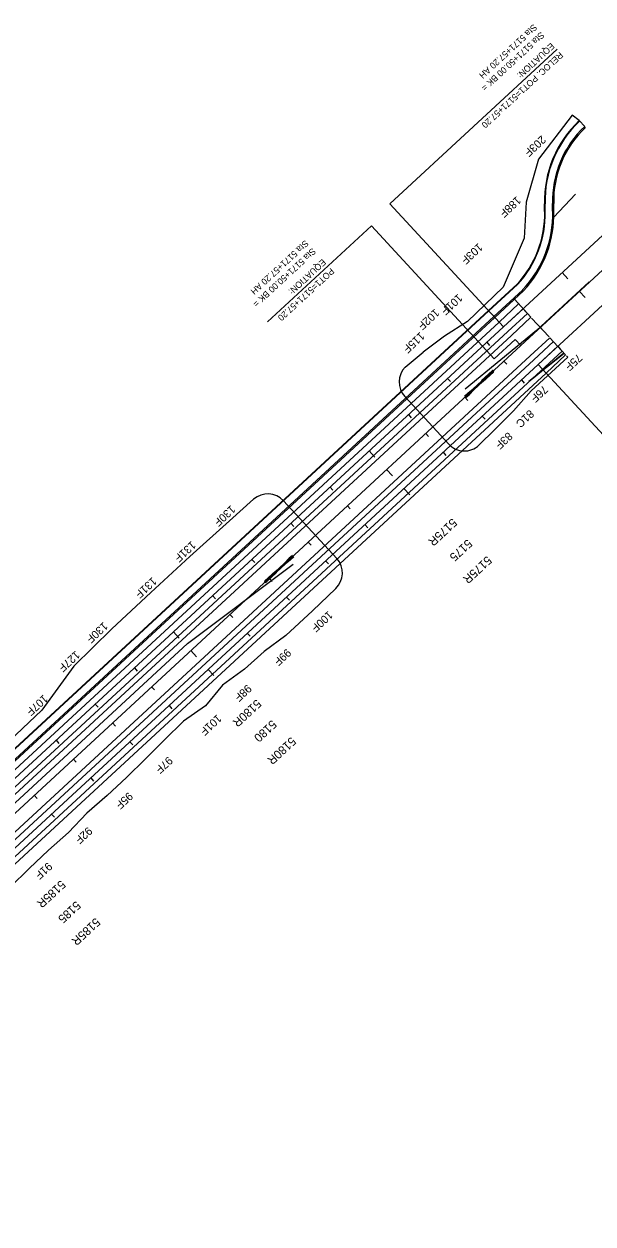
# Model space of a CAD drawing. Extents: x 2160876 to 2175625, y 601634 to 617693.
# Drawn here: x 2171308 to 2172375, y 612093 to 614343 of the extents above; entities that cross this region are included whole.
import ezdxf

# ---------------------------------------------------------------- set-up
doc = ezdxf.new("R2010")
doc.units = 0
for name, color, linetype in [('RD_HC_Cl', 7, 'Continuous'), ('RD_HC_CL_Rel', 7, 'Continuous'), ('RD_HC_Data', 7, 'Continuous'), ('RD_HC_Data_Rel', 7, 'Continuous'), ('RD_HC_Data_Tic', 7, 'Continuous'), ('RD_HC_Data_Tic_Rel', 7, 'Continuous'), ('RD_HC_TX_Rel_Sta50', 7, 'Continuous'), ('RD_HC_TX_Sta50', 7, 'Continuous'), ('RD_PD_CstnLmt', 7, 'Continuous'), ('RD_PD_Fence', 7, 'Continuous'), ('RD_PD_Final_LnLine', 7, 'Continuous'), ('RD_PD_Final_TrvlWay', 7, 'Continuous'), ('RD_PD_GR', 7, 'Continuous'), ('RD_PD_MedBWall', 7, 'Continuous'), ('RD_PD_MedGR', 7, 'Continuous')]:
    doc.layers.add(name, color=color, linetype=linetype)

msp = doc.modelspace()

# ---------------------------------------------------------------- linework, layer by layer
at = {"layer": 'RD_HC_Cl'}
for p, q in [((2172654, 614122.3), (2172239.9, 613739.9)), ((2172239.9, 613739.9), (2163704.8, 605858.6))]:
    msp.add_line(p, q, dxfattribs=at)
at = {"layer": 'RD_HC_CL_Rel'}
for p, q in [((2172621.5, 614157.6), (2172207.3, 613775.1)), ((2172686.6, 614087), (2172272.5, 613704.6)), ((2172207.3, 613775.1), (2170395.2, 612101.8)), ((2172272.5, 613704.6), (2170460.3, 612031.3))]:
    msp.add_line(p, q, dxfattribs=at)
at = {"layer": 'RD_HC_Data'}
for p, q in [((2171994.4, 614005.8), (2172308.2, 614295.6)), ((2171959.5, 613964.4), (2171764.8, 613784.6)), ((2172239.9, 613739.9), (2172229.2, 613751.5))]:
    msp.add_line(p, q, dxfattribs=at)
msp.add_lwpolyline([(2172229.2, 613751.5), (2172189.7, 613715.1), (2171959.5, 613964.4)], dxfattribs=at)
at = {"layer": 'RD_HC_Data_Rel'}
for p, q in [((2172207.3, 613775.1), (2171994.4, 614005.8)), ((2172630.4, 613317), (2172272.5, 613704.6))]:
    msp.add_line(p, q, dxfattribs=at)
at = {"layer": 'RD_HC_Data_Tic'}
for p, q in [((2172350.1, 613841.6), (2172360.9, 613829.9)), ((2172276.6, 613773.8), (2172282, 613767.9)), ((2172208.4, 613710.8), (2172213.9, 613705)), ((2172135, 613643), (2172140.4, 613637.1)), ((2172061.5, 613575.2), (2172066.9, 613569.3)), ((2171988, 613507.3), (2171998.9, 613495.6)), ((2171914.6, 613439.5), (2171920, 613433.6)), ((2171841.1, 613371.6), (2171846.5, 613365.8)), ((2171767.6, 613303.8), (2171773.1, 613297.9)), ((2171694.2, 613236), (2171699.6, 613230.1)), ((2171620.7, 613168.1), (2171631.6, 613156.4)), ((2171547.2, 613100.3), (2171552.7, 613094.4)), ((2171473.8, 613032.4), (2171479.2, 613026.6)), ((2171400.3, 612964.6), (2171405.7, 612958.7)), ((2171326.8, 612896.7), (2171332.2, 612890.9))]:
    msp.add_line(p, q, dxfattribs=at)
at = {"layer": 'RD_HC_Data_Tic_Rel'}
for p, q in [((2172317.5, 613876.9), (2172328.4, 613865.1)), ((2172244.1, 613809.1), (2172249.5, 613803.2)), ((2172175.9, 613746.1), (2172181.3, 613740.2)), ((2172309.2, 613738.5), (2172314.6, 613732.7)), ((2172102.4, 613678.3), (2172107.8, 613672.4)), ((2172241, 613675.6), (2172246.4, 613669.7)), ((2172028.9, 613610.4), (2172034.4, 613604.5)), ((2172167.5, 613607.7), (2172173, 613601.9)), ((2171955.5, 613542.6), (2171966.3, 613530.8)), ((2172094.1, 613539.9), (2172099.5, 613534)), ((2171882, 613474.7), (2171887.4, 613468.9)), ((2172020.6, 613472.1), (2172031.5, 613460.3)), ((2171808.5, 613406.9), (2171814, 613401)), ((2171947.1, 613404.2), (2171952.6, 613398.3)), ((2171735.1, 613339.1), (2171740.5, 613333.2)), ((2171873.7, 613336.4), (2171879.1, 613330.5)), ((2171661.6, 613271.2), (2171667, 613265.3)), ((2171800.2, 613268.5), (2171805.6, 613262.7)), ((2171588.1, 613203.4), (2171599, 613191.6)), ((2171726.7, 613200.7), (2171732.2, 613194.8)), ((2171514.7, 613135.5), (2171520.1, 613129.7)), ((2171653.3, 613132.8), (2171664.1, 613121.1)), ((2171441.2, 613067.7), (2171446.6, 613061.8)), ((2171579.8, 613065), (2171585.2, 613059.1)), ((2171367.7, 612999.9), (2171373.2, 612994)), ((2171506.3, 612997.2), (2171511.8, 612991.3)), ((2171432.9, 612929.3), (2171438.3, 612923.4)), ((2171359.4, 612861.5), (2171364.8, 612855.6))]:
    msp.add_line(p, q, dxfattribs=at)
at = {"layer": 'RD_PD_CstnLmt'}
for p, q in [((2172349.7, 614161.7), (2172336.3, 614172)), ((2172206.8, 613849.4), (2172139.8, 613785.1)), ((2172139.8, 613785.1), (2172097, 613757.8)), ((2172292.9, 613756.2), (2172260.3, 613791.4)), ((2172097, 613757.8), (2172056.7, 613727.8)), ((2172022.8, 613699.6), (2172056.7, 613727.8)), ((2172259.7, 613655.3), (2172327.9, 613718.3)), ((2172327.9, 613718.3), (2172325.5, 613720.9)), ((2172259.7, 613655.3), (2172226.5, 613617.6)), ((2172104.8, 613555.2), (2172022.2, 613644.6)), ((2172226.5, 613617.6), (2172190.9, 613582.4)), ((2172190.9, 613582.4), (2172161.4, 613553)), ((2171738.6, 613451.8), (2171693, 613411.5)), ((2171894.6, 613340.6), (2171794.5, 613449)), ((2171693, 613411.5), (2171618.9, 613344.3)), ((2171618.9, 613344.3), (2171545.4, 613276.7)), ((2171545.4, 613276.7), (2171472.5, 613208.6)), ((2171892.7, 613284.4), (2171848.8, 613242.9)), ((2171848.8, 613242.9), (2171798.8, 613196.4)), ((2171472.5, 613208.6), (2171401.2, 613138.6)), ((2171401.2, 613138.6), (2171341.1, 613056.4)), ((2171341.1, 613056.4), (2171268.6, 612987.6))]:
    msp.add_line(p, q, dxfattribs=at)
for points in [[(2172336.3, 614172), (2172273.2, 614089.5), (2172250.2, 614008.7), (2172246, 613941.4), (2172206.8, 613849.4)], [(2171798.8, 613196.4), (2171758.2, 613166.6), (2171721.2, 613133), (2171680.3, 613103.5), (2171648.3, 613064.5), (2171606.8, 613035.7)], [(2171606.8, 613035.7), (2171571.1, 613000.7), (2171535.8, 612965.3), (2171500.1, 612930.2), (2171463.5, 612896.1), (2171425.7, 612863.4), (2171391.4, 612826.9), (2171353.8, 612793.8), (2171317.4, 612759.5), (2171281.4, 612724.8)]]:
    msp.add_lwpolyline(points, dxfattribs=at)
for centre, start, end in [((2172051.6, 613671.8), 135.9419, 222.7195), ((2172134.2, 613582.3), 222.7195, 312.9079), ((2171765.1, 613421.9), 42.7195, 131.5105), ((2171865.2, 613313.5), 313.372, 42.7195)]:
    msp.add_arc(centre, 40, start, end, dxfattribs=at)
at = {"layer": 'RD_PD_Fence'}
msp.add_lwpolyline([(2172302, 613980.8), (2172342.6, 614023.6)], dxfattribs=at)
at = {"layer": 'RD_PD_Final_LnLine'}
for p, q in [((2172359.9, 614150.8), (2172349.7, 614161.7)), ((2172284.7, 613991.5), (2172284.4, 614005.6)), ((2172285.7, 613991.5), (2172285.4, 614005.6)), ((2172299.7, 613991.9), (2172299.4, 614006)), ((2172233, 613855.1), (2172179.3, 613805.5)), ((2172233.7, 613854.4), (2172180, 613804.8)), ((2172179.3, 613805.5), (2170367.1, 612132.2)), ((2172180, 613804.8), (2170367.8, 612131.4)), ((2172235.9, 613817.9), (2172199.2, 613784)), ((2172244.1, 613809.1), (2172207.3, 613775.1)), ((2172199.2, 613784), (2170387, 612110.6)), ((2172252.2, 613800.2), (2172215.5, 613766.3)), ((2172207.3, 613775.1), (2170395.2, 612101.8)), ((2172215.5, 613766.3), (2170403.3, 612093)), ((2172301, 613747.3), (2172264.3, 613713.4)), ((2172309.2, 613738.5), (2172272.5, 613704.6)), ((2172321.6, 613725.1), (2172255.3, 613672.4)), ((2172317.3, 613729.7), (2172261.1, 613677.8)), ((2172264.3, 613713.4), (2170452.2, 612040.1)), ((2172272.5, 613704.6), (2170460.3, 612031.3)), ((2172261.1, 613677.8), (2170468.4, 612022.5))]:
    msp.add_line(p, q, dxfattribs=at)
msp.add_lwpolyline([(2172261.1, 613677.8), (2172306.9, 613714.8), (2172320.8, 613726)], dxfattribs=at)
for centre, radius, start, end in [((2172491.3, 614010.7), 207, 133.1773, 181.4209), ((2172491.3, 614010.7), 206, 133.1773, 181.4209), ((2172491.3, 614010.7), 192, 133.1773, 181.4209), ((2172091.8, 613986.7), 193, 316.7496, 1.4209), ((2172091.8, 613986.7), 194, 317.041, 1.4209), ((2172091.8, 613986.7), 208, 316.7496, 1.4209)]:
    msp.add_arc(centre, radius, start, end, dxfattribs=at)
at = {"layer": 'RD_PD_Final_TrvlWay'}
for p, q in [((2172227.8, 613826.7), (2172191, 613792.8)), ((2172259, 613792.9), (2172227.8, 613826.7)), ((2172191, 613792.8), (2170378.9, 612119.4)), ((2172259, 613792.9), (2172222.2, 613759)), ((2172222.2, 613759), (2170410.1, 612085.6)), ((2172294.3, 613754.7), (2172257.5, 613720.8)), ((2172294.3, 613754.7), (2172324.1, 613722.4)), ((2172257.5, 613720.8), (2170445.4, 612047.4)), ((2172324.1, 613722.4), (2172287.4, 613688.4)), ((2172287.4, 613688.4), (2170475.2, 612015.1))]:
    msp.add_line(p, q, dxfattribs=at)
at = {"layer": 'RD_PD_GR'}
for p, q in [((2172368.3, 613859.5), (2172269.3, 613768)), ((2172269.3, 613768), (2172135.6, 613658.5)), ((2171614.4, 613181.4), (2171812.6, 613330.3)), ((2170418.2, 612076.8), (2171614.4, 613181.4))]:
    msp.add_line(p, q, dxfattribs=at)
at = {"layer": 'RD_PD_MedBWall'}
for p, q in [((2172302, 613991.9), (2172301.7, 614006)), ((2172243.2, 613844.1), (2172189.5, 613794.5)), ((2172244.9, 613842.5), (2172191, 613792.8)), ((2172189.5, 613794.5), (2170377.3, 612121.1)), ((2172191, 613792.8), (2170378.9, 612119.4)), ((2172150.6, 613659), (2172166.8, 613673.9)), ((2172152.2, 613657.3), (2172168.3, 613672.2)), ((2172168.3, 613672.2), (2172166.8, 613673.9)), ((2172137, 613642.3), (2172142.8, 613647.8)), ((2172142.8, 613647.8), (2172152.2, 613657.3)), ((2171807.8, 613338.4), (2171797.6, 613329.8)), ((2171813.7, 613343.8), (2171807.8, 613338.4)), ((2171796, 613331.6), (2171779.8, 613316.6)), ((2171781.4, 613314.9), (2171779.8, 613316.6)), ((2171797.6, 613329.8), (2171781.4, 613314.9))]:
    msp.add_line(p, q, dxfattribs=at)
for points in [[(2172134.5, 613645), (2172140.3, 613650.5), (2172150.6, 613659)], [(2171811.2, 613346.5), (2171805.3, 613341.1), (2171796, 613331.6)]]:
    msp.add_lwpolyline(points, dxfattribs=at)
for centre, radius, start, end in [((2172491.3, 614010.7), 189.7, 133.1773, 181.4209), ((2172091.8, 613986.7), 210.3, 316.7048, 1.4209)]:
    msp.add_arc(centre, radius, start, end, dxfattribs=at)
at = {"layer": 'RD_PD_MedGR'}
for p, q in [((2172166.4, 613674.3), (2172186.3, 613692.6)), ((2172166.4, 613674.3), (2172186.3, 613692.6)), ((2172169.7, 613676.6), (2172186.6, 613692.3)), ((2172188.5, 613690.2), (2172186.3, 613692.6)), ((2172186.5, 613692.3), (2172186.3, 613692.6)), ((2172166.4, 613674.3), (2172166.8, 613673.9)), ((2172166.8, 613673.9), (2172166.4, 613674.3)), ((2172166.8, 613673.9), (2172169.7, 613676.6)), ((2172169.7, 613676.6), (2172166.8, 613673.9)), ((2172168.3, 613672.2), (2172171.3, 613674.9)), ((2172168.3, 613672.2), (2172171.3, 613674.9)), ((2172168.7, 613671.9), (2172168.3, 613672.2)), ((2172168.7, 613671.9), (2172168.3, 613672.2)), ((2172168.7, 613671.9), (2172188.5, 613690.2)), ((2172188.5, 613690.2), (2172168.7, 613671.9)), ((2172171.2, 613678), (2172169.7, 613676.6)), ((2172171.3, 613674.9), (2172169.7, 613676.6)), ((2172171.5, 613678.3), (2172171.2, 613678)), ((2172172.7, 613676.3), (2172171.2, 613678)), ((2172171.3, 613674.9), (2172188.2, 613690.5)), ((2172173.4, 613680), (2172171.5, 613678.3)), ((2172173, 613676.6), (2172171.5, 613678.3)), ((2172173.7, 613680.3), (2172173.4, 613680)), ((2172174.9, 613678.3), (2172173.4, 613680)), ((2172175.6, 613682.1), (2172173.7, 613680.3)), ((2172175.2, 613678.6), (2172173.7, 613680.3)), ((2172175.9, 613682.3), (2172175.6, 613682.1)), ((2172177.2, 613680.4), (2172175.6, 613682.1)), ((2172177.8, 613684.1), (2172175.9, 613682.3)), ((2172177.4, 613680.6), (2172175.9, 613682.3)), ((2172178.1, 613684.4), (2172177.8, 613684.1)), ((2172179.4, 613682.4), (2172177.8, 613684.1)), ((2172180, 613686.1), (2172178.1, 613684.4)), ((2172179.7, 613682.7), (2172178.1, 613684.4)), ((2172180.3, 613686.4), (2172180, 613686.1)), ((2172181.6, 613684.4), (2172180, 613686.1)), ((2172182.2, 613688.2), (2172180.3, 613686.4)), ((2172181.9, 613684.7), (2172180.3, 613686.4)), ((2172182.5, 613688.5), (2172182.2, 613688.2)), ((2172183.8, 613686.5), (2172182.2, 613688.2)), ((2172184.4, 613690.2), (2172182.5, 613688.5)), ((2172184.1, 613686.7), (2172182.5, 613688.5)), ((2172186, 613688.5), (2172184.4, 613690.2)), ((2172186.3, 613688.8), (2172184.7, 613690.5)), ((2172188.5, 613690.2), (2172188.2, 613690.5)), ((2171779.5, 613317), (2171759.6, 613298.7)), ((2171779.5, 613317), (2171759.6, 613298.7)), ((2171776.9, 613313.9), (2171760, 613298.3)), ((2171778.5, 613312.2), (2171761.6, 613296.6)), ((2171781.7, 613314.6), (2171761.9, 613296.2)), ((2171761.9, 613296.2), (2171781.7, 613314.6)), ((2171771, 613308.5), (2171772.9, 613310.3)), ((2171772.9, 613310.3), (2171773.2, 613310.5)), ((2171774.5, 613308.5), (2171772.9, 613310.3)), ((2171773.2, 613310.5), (2171775.1, 613312.3)), ((2171774.8, 613308.8), (2171773.2, 613310.5)), ((2171775.1, 613312.3), (2171775.4, 613312.6)), ((2171776.7, 613310.6), (2171775.1, 613312.3)), ((2171775.4, 613312.6), (2171776.9, 613313.9)), ((2171777, 613310.9), (2171775.4, 613312.6)), ((2171779.8, 613316.6), (2171776.9, 613313.9)), ((2171776.9, 613313.9), (2171779.8, 613316.6)), ((2171778.5, 613312.2), (2171776.9, 613313.9)), ((2171781.4, 613314.9), (2171778.5, 613312.2)), ((2171781.4, 613314.9), (2171778.5, 613312.2)), ((2171779.5, 613317), (2171779.8, 613316.6)), ((2171779.8, 613316.6), (2171779.5, 613317)), ((2171781.7, 613314.6), (2171781.4, 613314.9)), ((2171781.7, 613314.6), (2171781.4, 613314.9)), ((2171761.9, 613296.2), (2171759.6, 613298.7)), ((2171759.9, 613298.4), (2171759.6, 613298.7)), ((2171761.9, 613296.2), (2171761.6, 613296.5)), ((2171763.5, 613298.4), (2171761.9, 613300.1)), ((2171762.2, 613300.4), (2171764.1, 613302.1)), ((2171763.8, 613298.6), (2171762.2, 613300.4)), ((2171764.1, 613302.1), (2171764.4, 613302.4)), ((2171765.7, 613300.4), (2171764.1, 613302.1)), ((2171764.4, 613302.4), (2171766.3, 613304.2)), ((2171766, 613300.7), (2171764.4, 613302.4)), ((2171766.3, 613304.2), (2171766.6, 613304.4)), ((2171767.9, 613302.4), (2171766.3, 613304.2)), ((2171766.6, 613304.4), (2171768.5, 613306.2)), ((2171768.2, 613302.7), (2171766.6, 613304.4)), ((2171768.5, 613306.2), (2171768.8, 613306.5)), ((2171770.1, 613304.5), (2171768.5, 613306.2)), ((2171768.8, 613306.5), (2171770.7, 613308.2)), ((2171770.4, 613304.7), (2171768.8, 613306.5)), ((2171770.7, 613308.2), (2171771, 613308.5)), ((2171772.3, 613306.5), (2171770.7, 613308.2)), ((2171772.6, 613306.8), (2171771, 613308.5))]:
    msp.add_line(p, q, dxfattribs=at)
for points in [[(2172186.6, 613692.3), (2172184.7, 613690.5), (2172184.4, 613690.2)], [(2172186.3, 613692.6), (2172186.5, 613692.3), (2172186.6, 613692.3)], [(2172171.3, 613674.9), (2172172.7, 613676.3), (2172173, 613676.6), (2172174.9, 613678.3), (2172175.2, 613678.6), (2172177.2, 613680.4), (2172177.4, 613680.6), (2172179.4, 613682.4), (2172179.7, 613682.7), (2172181.6, 613684.4), (2172181.9, 613684.7), (2172183.8, 613686.5), (2172184.1, 613686.7), (2172186, 613688.5), (2172186.3, 613688.8), (2172188.2, 613690.5)], [(2172188.2, 613690.5), (2172188.2, 613690.5), (2172188.5, 613690.2)], [(2171778.5, 613312.2), (2171777, 613310.9), (2171776.7, 613310.6), (2171774.8, 613308.8), (2171774.5, 613308.5), (2171772.6, 613306.8), (2171772.3, 613306.5), (2171770.4, 613304.7), (2171770.1, 613304.5), (2171768.2, 613302.7), (2171767.9, 613302.4), (2171766, 613300.7), (2171765.7, 613300.4), (2171763.8, 613298.6), (2171763.5, 613298.4), (2171761.6, 613296.6)], [(2171759.6, 613298.7), (2171759.9, 613298.4), (2171760, 613298.3)], [(2171760, 613298.3), (2171761.9, 613300.1), (2171762.2, 613300.4)], [(2171761.6, 613296.6), (2171761.6, 613296.5), (2171761.9, 613296.2)]]:
    msp.add_lwpolyline(points, dxfattribs=at)
for centre, radius, start, end in [((2172187.4, 613691.4), 1.67, 312.7195, 132.7195), ((2172187.4, 613691.4), 1.67, 312.7195, 132.7195), ((2172187.4, 613691.4), 1.27, 312.7195, 132.7195), ((2172187.4, 613691.4), 1.27, 312.7195, 132.7195), ((2171760.8, 613297.5), 1.67, 132.7195, 312.7195), ((2171760.8, 613297.5), 1.67, 132.7195, 312.7195), ((2171760.8, 613297.5), 1.27, 132.7195, 312.7195), ((2171760.8, 613297.5), 1.27, 132.7195, 312.7195)]:
    msp.add_arc(centre, radius, start, end, dxfattribs=at)

# ---------------------------------------------------------------- texts
at = {"layer": 'RD_HC_Data'}
for s, p in [('Sta 5171+57.20 AH', (2171835, 613938.5)), ('Sta 5171+50.00 BK = ', (2171848.6, 613923.8)), ('EQUATION:', (2171867.6, 613903.2)), ('POT1=5171+57.20', (2171883.1, 613886.4))]:
    msp.add_text(s, height=12, rotation=222.7195, dxfattribs=at).set_placement(p)
at = {"layer": 'RD_HC_Data_Rel'}
for s, p in [('Sta 5171+57.20 AH', (2172263.8, 614343.6)), ('Sta 5171+50.00 BK = ', (2172277.4, 614328.9)), ('EQUATION:', (2172296.4, 614308.4)), ('RELOC. POT1=5171+57.20', (2172312.7, 614291.5))]:
    msp.add_text(s, height=12, rotation=222.7195, dxfattribs=at).set_placement(p)
at = {"layer": 'RD_HC_TX_Rel_Sta50'}
for s, p in [('5175R', (2172111.3, 613417)), ('5175R', (2172176.5, 613346.5)), ('5180R', (2171744, 613077.8)), ('5180R', (2171809.1, 613007.3)), ('5185R', (2171376.7, 612738.6)), ('5185R', (2171441.8, 612668.1))]:
    msp.add_text(s, height=16, rotation=222.7195, dxfattribs=at).set_placement(p)
at = {"layer": 'RD_HC_TX_Sta50'}
for s, p in [('5175', (2172139.8, 613377.9)), ('5180', (2171772.8, 613039)), ('5185', (2171405.1, 612699.5))]:
    msp.add_text(s, height=16, rotation=222.7195, dxfattribs=at).set_placement(p)
at = {"layer": 'RD_PD_CstnLmt'}
for s, rotation, p in [('203F', 222.7195, (2172278.7, 614134.8)), ('188F', 222.7195, (2172232.2, 614020.8)), ('103F', 222.7195, (2172160.2, 613932.9)), ('101F', 222.7195, (2172122.4, 613837.9)), ('102F', 222.7195, (2172078.9, 613810)), ('115F', 222.7195, (2172051.3, 613766.4)), ('75F', 222.7195, (2172346.8, 613725.7)), ('76F', 222.7195, (2172282.6, 613666.4)), ('81C', 222.7195, (2172256.4, 613620.6)), ('83F', 222.7195, (2172216, 613578.7)), ('130F', 222.7195, (2171696.1, 613441.5)), ('131F', 222.7195, (2171622, 613374.4)), ('131F', 222.6747, (2171548.5, 613306.8)), ('100F', 222.7195, (2171879, 613243.5)), ('130F', 222.5962, (2171456.8, 613222.5)), ('127F', 222.5177, (2171404.4, 613168.6)), ('99F', 222.7195, (2171800.6, 613172.7)), ('107F', 222.4392, (2171344.3, 613086.4)), ('98F', 222.6747, (2171726.4, 613105.5)), ('101F', 222.5962, (2171670.3, 613049.4)), ('97F', 222.5177, (2171578.4, 612970.5)), ('95F', 222.4392, (2171503.7, 612903.7)), ('92F', 222.3607, (2171427.6, 612838.6)), ('91F', 222.2822, (2171352.5, 612772.2))]:
    msp.add_text(s, height=15, rotation=rotation, dxfattribs=at).set_placement(p)

doc.saveas('drawing.dxf')
